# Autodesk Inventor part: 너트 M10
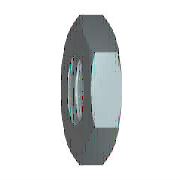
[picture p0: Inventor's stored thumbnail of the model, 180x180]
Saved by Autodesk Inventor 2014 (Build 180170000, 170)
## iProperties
IsCustomPart: 1
Created: 2012-02
Part Number: 너트 M10
Material: 스테인리스강
Description: 미터법 정밀 피치 스레드가 있는 6각 가는 너트(모따기됨)
Document SubType Name: Modeling
Standard: ISO 8675
Designer: mduedu
Standard Revision: Second edition 1999-08-15
Standards Organization: ISO
Language: ko-KR
Size Designation: M10 x 1
Categories: <MemberInstance><Categories><Category DisplayName="조임쇠" InternalName="e4da775c-781d-43d5-af7c-5136215cf5a6" Mnemonic="FSTN"><Category DisplayName="너트" InternalN
Density: 8.08 g/cm^3
Appearance: Default
Author: mduedu
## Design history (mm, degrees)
sketch "스케치1"
  geometry: L1 (-9.238, 0)-(-4.619, 8); L2 (-4.619, 8)-(4.619, 8); L3 (4.619, 8)-(9.238, 0); L4 (9.238, 0)-(4.619, -8); L5 (4.619, -8)-(-4.619, -8); L6 (-4.619, -8)-(-9.238, 0); 2 further points
  constraints: 12 end point, 1 coincident, 1 horizontal, 11 other
  dimensions: "d0" = 18.47521 distance of L3.end L1.start (= 1.1547 x SW)
extrude "본체" new body sketch "스케치1" distance "d1" = 5 (= KOH); taper "d2" = 0 deg
sketch "스케치2"
  geometry: L1 (0, 4.619)-(0, 9.238) reference; L2 (0, 9.238)-(5, 9.238) reference; L3 (5, 4.619)-(5, 9.238) reference; L4 (-1, 0)-(6, 0) reference; L5 (1.11, 9.238)-(0, 7.315); L6 (3.89, 9.238)-(5, 7.315)
  constraints: 4 end point, 4 point on line
  dimensions: "d3" = 30 deg angle of L1 L5 (= ANG1); "d4" = 30 deg angle of L3 L6 (= ANG2); "d5" = 14.63 diameter of L5.end L4 (= SW0); "d6" = 14.63 diameter of L6.end L4 (= SW01)
revolve "모따기1" sketch "스케치2" stored, may be unused: angle "d7" = 90 deg
sketch "스케치3"
  geometry: 4 further points
  constraints: 1 coincident, 1 other
hole "스레드" sketch "스케치3" at (0, 0) diameter "d25" = 8.91747; stored, may be unused: countersink angle "d29" = 82 deg, drill point angle "d31" = 118 deg; dims "d26" = 6, "d27" = 4, "d28" = 2, "d30" = 8
workaxis "Work Axis1"
workplane "Work Plane1"
body "Solid1"
chamfer "모따기2" distance "d8" = 0.54127 (= -0.5 x GD1 + 0.5 x NND); stored, may be unused: angle "d9" = 30 deg, second distance "d40" = 0.54127 (= -0.5 x GD1 + 0.5 x NND)
chamfer "모따기3" distance "d10" = 0.54127 (= -0.5 x GD1 + 0.5 x NND); stored, may be unused: angle "d11" = 30 deg, second distance "d41" = 0.54127 (= -0.5 x GD1 + 0.5 x NND)
other parameters: "ANG1" = 30 deg [user parameter; used in 1 equation term], "ANG2" = 30 deg [user parameter; used in 1 equation term], "KOH" = 5 [user parameter; used in 1 equation term], "SW" = 16 [user parameter; used in 1 equation term], "SW0" = 14.63 [user parameter; used in 2 equation terms], "SW01" = 14.63 (= SW0) [user parameter; used in 1 equation term], "GD1" = 8.91747 (computed from THREADDIA, PTC, TOA) [user parameter; used in 4 equation terms], "d13" = 0, "d14" = 0, "d39" = 0, "d42" = 0, "GUL" = 0.54127 (= 0.541266 x PTC) [user parameter], "TOA" = 30 deg [user parameter; used in 1 equation term], "PTC" = 1 [user parameter; used in 4 equation terms], "E0" = 17.77 [user parameter], "GAL" = 0.54127 (= 0.541266 x PTC) [user parameter]
